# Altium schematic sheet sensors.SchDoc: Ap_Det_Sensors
size A; Revision: 1.2; SheetNumber: 2; SheetTotal: 2
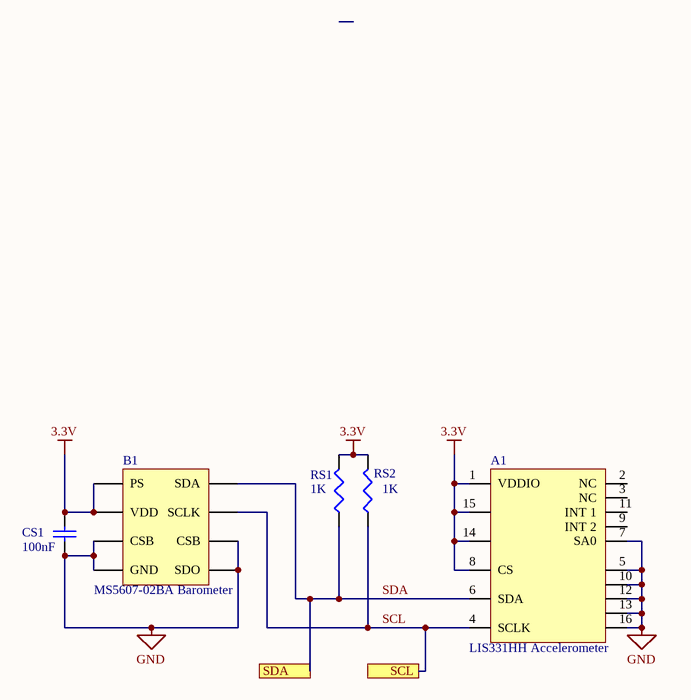
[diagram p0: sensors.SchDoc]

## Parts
A1  LIS331HH Accelerometer  [LGA16]
B1  MS5607-02BA Barometer  [Barometer LCC]
CS1  value 100nF  [C1206]  (hidden comment: Cap Semi)
RS1  value 1K  [J1-0603]  (hidden comment: Res3)
RS2  value 1K  [J1-0603]  (hidden comment: Res3)

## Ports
SCL, SDA

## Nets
3.3V: A1.1(VDDIO) A1.8(CS) A1.14 A1.15 B1.1(VDD) B1.2(PS) CS1.2 RS1.2 RS2.2
GND: A1.5(GND) A1.7(SA0) A1.10 A1.12 A1.13 A1.16 B1.3(GND) B1.4(CSB) B1.5(CSB) B1.6(SDO) CS1.1
SCL: A1.4(SCLK) B1.8(SCLK) RS2.1 ; port SCL
SDA: A1.6(SDA) B1.7(SDA) RS1.1 ; port SDA

Not connected (* = marked no-connect by the designer): A1 2(NC) 3(NC) 9(INT_2) 11(INT_1)

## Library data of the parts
CS1 = Cap Semi: Capacitor (Semiconductor SIM Model)
RS1 RS2 = Res3: Resistor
